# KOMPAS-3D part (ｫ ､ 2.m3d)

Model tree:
1. Эскиз:1
2. Операция выдавливания:1
     Расстояние 1 = 20
3. Эскиз:2
4. Операция выдавливания:2
     Расстояние 1 = 400
5. Эскиз:3
6. Вырезать элемент выдавливания:1
     Расстояние 1 = 70
7. Эскиз:4
8. Вырезать элемент выдавливания:2
     Расстояние 1 = 2
9. Эскиз:5
10. Эскиз:11
11. Вырезать элемент выдавливания:7
     Расстояние 1 = 30
12. Операция выдавливания:3
     Расстояние 1 = 16.96
13. Эскиз:13
14. Вырезать элемент выдавливания:9
     Расстояние 1 = 70
15. Эскиз:14
16. Вырезать элемент выдавливания:10
     Расстояние 1 = 80
